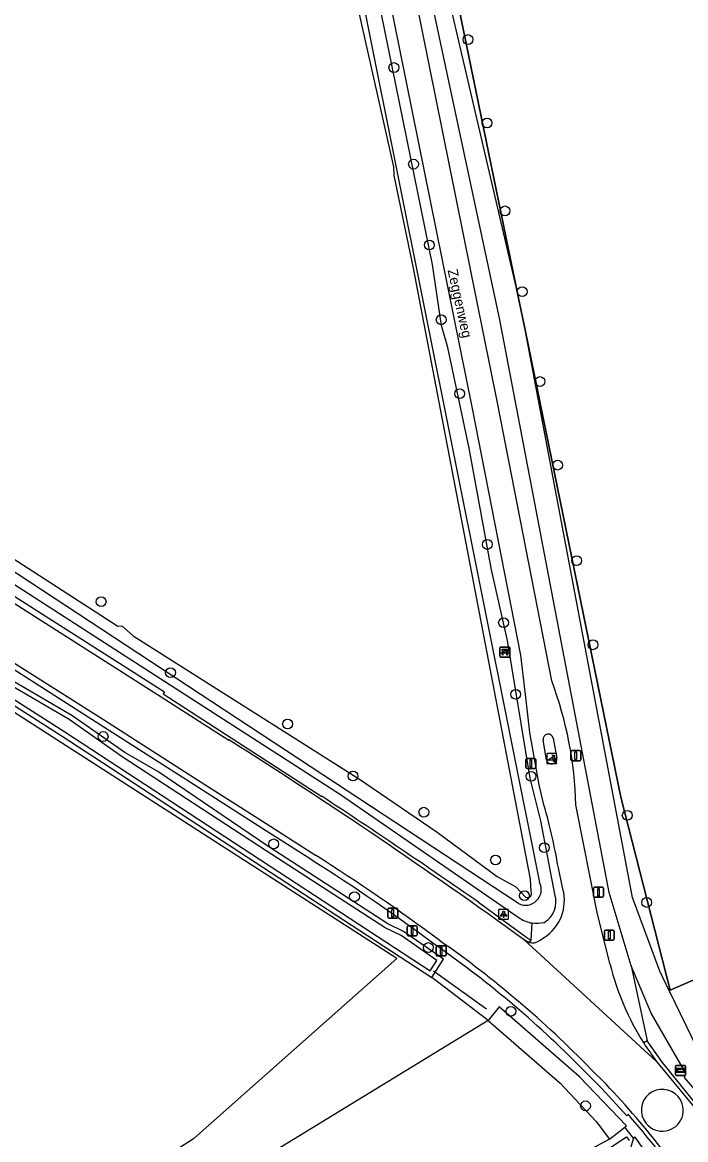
# Model space of a CAD drawing. Extents: x 164494 to 166241, y 382475 to 384494.
# Drawn here: x 165322.7 to 165388.9, y 382859.1 to 382970.6 of the extents above; entities that cross this region are included whole.
import ezdxf

# ---------------------------------------------------------------- set-up
doc = ezdxf.new("R2010")
doc.units = 0
for name, color, linetype in [('IMGEO_Afsluitpaal', 7, 'Continuous'), ('IMGEO_Bank', 7, 'Continuous'), ('IMGEO_Berm_halfverhard', 7, 'Continuous'), ('IMGEO_Boom', 7, 'Continuous'), ('IMGEO_Duiker', 7, 'Continuous'), ('IMGEO_Grasland_agrarisch', 7, 'Continuous'), ('IMGEO_Grasland_overig', 7, 'Continuous'), ('IMGEO_Groenvoorziening', 7, 'Continuous'), ('IMGEO_Hek', 7, 'Continuous'), ('IMGEO_Lichtpunt', 7, 'Continuous'), ('IMGEO_Loofbos', 7, 'Continuous'), ('IMGEO_Openbare_ruimte_label', 7, 'Continuous'), ('IMGEO_Poller', 7, 'Continuous'), ('IMGEO_Rijbaan_lokaal_gesloten', 7, 'Continuous'), ('IMGEO_Rijbaan_lokaal_open', 7, 'Continuous'), ('IMGEO_Verkeersbordpaal', 7, 'Continuous'), ('IMGEO_Waterloop', 7, 'Continuous'), ('IMGEO_Wegwijzer', 7, 'Continuous')]:
    doc.layers.add(name, color=color, linetype=linetype)

msp = doc.modelspace()

# ---------------------------------------------------------------- linework, layer by layer
at = {"layer": 'IMGEO_Afsluitpaal'}
for p, q in [((165377.39, 382897.04), (165377.39, 382897.84)), ((165377.39, 382897.84), (165377.39, 382897.04)), ((165377.49, 382897.94), (165378.28, 382897.94)), ((165378.28, 382897.94), (165377.49, 382897.94)), ((165378.38, 382897.84), (165378.38, 382897.04)), ((165378.38, 382897.04), (165378.38, 382897.84)), ((165372.91, 382896.26), (165372.91, 382897.06)), ((165372.91, 382897.06), (165372.91, 382896.26)), ((165373.01, 382897.16), (165373.8, 382897.16)), ((165373.8, 382897.16), (165373.01, 382897.16)), ((165373.8, 382896.16), (165373.01, 382896.16)), ((165373.01, 382896.16), (165373.8, 382896.16)), ((165373.9, 382897.06), (165373.9, 382896.26)), ((165373.9, 382896.26), (165373.9, 382897.06)), ((165378.28, 382896.94), (165377.49, 382896.94)), ((165377.49, 382896.94), (165378.28, 382896.94)), ((165359.14, 382881.34), (165359.14, 382882.14)), ((165359.14, 382882.14), (165359.14, 382881.34)), ((165359.24, 382882.24), (165360.02, 382882.24)), ((165360.02, 382882.24), (165359.24, 382882.24)), ((165360.12, 382882.14), (165360.12, 382881.34)), ((165360.12, 382881.34), (165360.12, 382882.14)), ((165360.02, 382881.24), (165359.24, 382881.24)), ((165359.24, 382881.24), (165360.02, 382881.24)), ((165361.07, 382879.57), (165361.07, 382880.37)), ((165361.07, 382880.37), (165361.07, 382879.57)), ((165361.17, 382880.47), (165361.95, 382880.47)), ((165361.95, 382880.47), (165361.17, 382880.47)), ((165361.95, 382879.47), (165361.17, 382879.47)), ((165361.17, 382879.47), (165361.95, 382879.47)), ((165362.05, 382880.37), (165362.05, 382879.57)), ((165362.05, 382879.57), (165362.05, 382880.37)), ((165363.96, 382877.56), (165363.96, 382878.36)), ((165363.96, 382878.36), (165363.96, 382877.56)), ((165364.06, 382878.46), (165364.85, 382878.46)), ((165364.85, 382878.46), (165364.06, 382878.46)), ((165364.95, 382878.36), (165364.95, 382877.56)), ((165364.95, 382877.56), (165364.95, 382878.36)), ((165364.85, 382877.46), (165364.06, 382877.46)), ((165364.06, 382877.46), (165364.85, 382877.46))]:
    msp.add_line(p, q, dxfattribs=at)
for points in [[(165377.81, 382897.81), (165377.96, 382897.81), (165377.96, 382897.06), (165377.81, 382897.06), (165377.81, 382897.81)], [(165373.33, 382897.03), (165373.48, 382897.03), (165373.48, 382896.28), (165373.33, 382896.28), (165373.33, 382897.03)], [(165359.55, 382882.11), (165359.71, 382882.11), (165359.71, 382881.36), (165359.55, 382881.36), (165359.55, 382882.11)], [(165361.49, 382880.35), (165361.64, 382880.35), (165361.64, 382879.6), (165361.49, 382879.6), (165361.49, 382880.35)], [(165364.38, 382878.34), (165364.53, 382878.34), (165364.53, 382877.59), (165364.38, 382877.59), (165364.38, 382878.34)]]:
    msp.add_lwpolyline(points, dxfattribs=at)
for centre, start, end in [((165377.49, 382897.84), 90, 180), ((165377.49, 382897.84), 90, 180), ((165378.28, 382897.84), 0, 90), ((165378.28, 382897.84), 360, 90), ((165373.01, 382897.06), 90, 180), ((165373.01, 382897.06), 90, 180), ((165373.01, 382896.26), 180, 270), ((165373.01, 382896.26), 180, 270), ((165373.8, 382897.06), 0, 90), ((165373.8, 382897.06), 360, 90), ((165373.8, 382896.26), 270, 0), ((165373.8, 382896.26), 270, 0), ((165377.49, 382897.04), 180, 270), ((165377.49, 382897.04), 180, 270), ((165378.28, 382897.04), 270, 0), ((165378.28, 382897.04), 270, 0), ((165359.24, 382882.14), 90, 180), ((165359.24, 382882.14), 90, 180), ((165360.02, 382882.14), 0, 90), ((165360.02, 382882.14), 360, 90), ((165359.24, 382881.34), 180, 270), ((165359.24, 382881.34), 180, 270), ((165360.02, 382881.34), 270, 0), ((165360.02, 382881.34), 270, 0), ((165361.17, 382880.37), 90, 180), ((165361.17, 382880.37), 90, 180), ((165361.17, 382879.57), 180, 270), ((165361.17, 382879.57), 180, 270), ((165361.95, 382880.37), 0, 90), ((165361.95, 382880.37), 360, 90), ((165361.95, 382879.57), 270, 0), ((165361.95, 382879.57), 270, 0), ((165364.06, 382878.36), 90, 180), ((165364.06, 382878.36), 90, 180), ((165364.85, 382878.36), 0, 90), ((165364.85, 382878.36), 360, 90), ((165364.06, 382877.56), 180, 270), ((165364.06, 382877.56), 180, 270), ((165364.85, 382877.56), 270, 0), ((165364.85, 382877.56), 270, 0)]:
    msp.add_arc(centre, 0.1, start, end, dxfattribs=at)
at = {"layer": 'IMGEO_Bank'}
for p, q in [((165370.32, 382907.35), (165370.32, 382908.19)), ((165370.32, 382908.19), (165370.32, 382907.35)), ((165370.39, 382908.27), (165371.23, 382908.27)), ((165371.23, 382908.27), (165370.39, 382908.27)), ((165370.62, 382907.78), (165370.62, 382907.88)), ((165371.01, 382907.67), (165370.62, 382907.67)), ((165370.96, 382907.89), (165370.67, 382907.89)), ((165370.67, 382907.88), (165370.67, 382907.78)), ((165370.67, 382907.77), (165370.96, 382907.77)), ((165370.96, 382907.78), (165370.96, 382907.88)), ((165371.01, 382907.88), (165371.01, 382907.78)), ((165371.31, 382908.2), (165371.31, 382907.36)), ((165371.31, 382907.36), (165371.31, 382908.2)), ((165371.24, 382907.27), (165370.4, 382907.27)), ((165370.4, 382907.27), (165371.24, 382907.27))]:
    msp.add_line(p, q, dxfattribs=at)
for points in [[(165370.56, 382907.67), (165370.42, 382907.67), (165370.53, 382907.77), (165370.62, 382907.77)], [(165370.62, 382907.89), (165370.53, 382907.89), (165370.53, 382908.05), (165371.1, 382908.05), (165371.1, 382907.89), (165371.01, 382907.89)], [(165370.61, 382907.66), (165370.61, 382907.46), (165370.57, 382907.46), (165370.57, 382907.66)], [(165371.01, 382907.77), (165371.1, 382907.77), (165371.21, 382907.67), (165371.07, 382907.67)], [(165371.06, 382907.66), (165371.06, 382907.46), (165371.02, 382907.46), (165371.02, 382907.66)]]:
    msp.add_lwpolyline(points, dxfattribs=at)
for centre, radius, start, end in [((165370.39, 382908.19), 0.0779, 92.4484, 184.2845), ((165370.39, 382908.19), 0.0779, 92.4484, 184.2845), ((165370.39, 382907.35), 0.0779, 182.4484, 274.2845), ((165370.39, 382907.35), 0.0779, 182.4484, 274.2845), ((165370.56, 382907.66), 0.00671, 2.8957, 87.1043), ((165370.62, 382907.66), 0.00671, 92.8957, 177.1043), ((165370.62, 382907.88), 0.00671, 2.8957, 87.1043), ((165370.62, 382907.78), 0.00671, 272.8957, 357.1043), ((165370.67, 382907.88), 0.00671, 92.8957, 177.1043), ((165370.67, 382907.78), 0.00671, 182.8957, 267.1043), ((165370.96, 382907.88), 0.00671, 2.8957, 87.1043), ((165370.96, 382907.78), 0.00671, 272.8957, 357.1043), ((165371.01, 382907.88), 0.00671, 92.8957, 177.1043), ((165371.01, 382907.78), 0.00671, 182.8957, 267.1043), ((165371.01, 382907.66), 0.00671, 2.8957, 87.1043), ((165371.07, 382907.66), 0.00671, 92.8957, 177.1043), ((165371.24, 382908.19), 0.0779, 2.4484, 94.2845), ((165371.24, 382908.19), 0.0779, 2.4484, 94.2845), ((165371.24, 382907.35), 0.0779, 272.4484, 4.2845), ((165371.24, 382907.35), 0.0779, 272.4484, 4.2845)]:
    msp.add_arc(centre, radius, start, end, dxfattribs=at)
at = {"layer": 'IMGEO_Berm_halfverhard'}
for points in [[(165252.94, 382956.51), (165253.27, 382957.02), (165336.85, 382903.81), (165336.73, 382903.62), (165352.54, 382893.38)], [(165351.59, 382887), (165346.66, 382890.15), (165339.82, 382894.53), (165330.45, 382900.53), (165322.57, 382905.52), (165313.17, 382911.49), (165304.23, 382917.2), (165295.7, 382922.63), (165290.59, 382925.86), (165282.82, 382930.8), (165276, 382935.15), (165269.08, 382939.56), (165261.99, 382944.04), (165250.07, 382951.57), (165250.4, 382952.08)], [(165368.18, 382882.81), (165373.02, 382879.3), (165373.39, 382879.04)], [(165373.39, 382879.04), (165373.23, 382878.8)], [(165385.01, 382868.98), (165384.67, 382868.78)], [(165405.31, 382840.85), (165405.7, 382841.13), (165395.37, 382856.06), (165395.18, 382855.94), (165395.15, 382855.99), (165390.91, 382861.46), (165386.55, 382866.83), (165385.01, 382868.98)], [(165383.14, 382861.64), (165382.99, 382861.5), (165380.49, 382864.24), (165378.96, 382865.76)]]:
    msp.add_lwpolyline(points, dxfattribs=at)
for centre, radius, start, end in [((165012.37, 382373.04), 621.67, 55.08545, 56.82581), ((165250.17, 382726.04), 190.24, 53.257, 57.7856), ((165304.44, 382793.22), 104, 44.2296, 55.0756), ((165318.7, 382805.39), 85.53, 37.6329, 41.118)]:
    msp.add_arc(centre, radius, start, end, dxfattribs=at)
at = {"layer": 'IMGEO_Boom'}
for centre in [(165367.14, 382968.87), (165359.74, 382966.08), (165369.04, 382960.55), (165361.7, 382956.44), (165370.82, 382951.78), (165363.27, 382948.38), (165372.54, 382943.73), (165364.46, 382940.92), (165374.32, 382934.76), (165366.3, 382933.55), (165376.09, 382926.42), (165369.06, 382918.51), (165377.98, 382916.9), (165330.53, 382912.8), (165370.68, 382910.71), (165379.6, 382908.5), (165337.45, 382905.72), (165371.89, 382903.55), (165349.13, 382900.6), (165330.73, 382899.35), (165355.66, 382895.41), (165373.43, 382895.38), (165362.73, 382891.8), (165383.02, 382891.48), (165347.74, 382888.64), (165374.75, 382888.26), (165369.88, 382887.04), (165372.77, 382883.47), (165355.81, 382883.38), (165384.96, 382882.8), (165363.17, 382878.3), (165371.41, 382871.94), (165378.86, 382862.51)]:
    msp.add_circle(centre, 0.489, dxfattribs=at)
at = {"layer": 'IMGEO_Duiker'}
msp.add_lwpolyline([(165363.68, 382875.99), (165368.98, 382872.18)], dxfattribs=at)
at = {"layer": 'IMGEO_Grasland_agrarisch'}
for points in [[(165373.43, 382883.9), (165373.38, 382885.12), (165361.69, 382946.07), (165359.77, 382955.3), (165359.73, 382956.18), (165356.23, 382971.7), (165355.68, 382973.4), (165355.57, 382974.98), (165351.45, 382995.91), (165350.65, 383000), (165350.07, 383002.18), (165350.07, 383003.02), (165348.36, 383010.36), (165348.14, 383011.31), (165347.08, 383015.04), (165345.31, 383024.57), (165344.87, 383027.57), (165344.77, 383029.04)], [(165240.44, 382969.54), (165240.65, 382969.41), (165269.04, 382951.11), (165283.23, 382941.96), (165296.82, 382933.2), (165304.27, 382928.28), (165316.97, 382920.29), (165318.03, 382919.42), (165318.5, 382918.84), (165319.92, 382918.27), (165332.19, 382910.35), (165332.59, 382910.4), (165333.72, 382909.38), (165356.3, 382895.09), (165364.07, 382889.81), (165370.04, 382885.4), (165371.91, 382884.35), (165372.87, 382883.34)], [(165372.86, 382939.74), (165382.4, 382893.29), (165387.31, 382874.04)]]:
    msp.add_lwpolyline(points, dxfattribs=at)
msp.add_arc((165373.07, 382883.7), 0.412, 240.6912, 28.6949, dxfattribs=at)
at = {"layer": 'IMGEO_Grasland_overig'}
for points in [[(165362.51, 382988.43), (165363.72, 382984.2), (165372.17, 382943.09)], [(165373.5, 382880.75), (165373.39, 382879.04)], [(165383.4, 382876.48), (165385.01, 382868.98)], [(165388.88, 382865.77), (165388.7, 382865.33), (165390.11, 382863.71), (165390.42, 382863.86)]]:
    msp.add_lwpolyline(points, dxfattribs=at)
at = {"layer": 'IMGEO_Groenvoorziening'}
for points in [[(165363.51, 382875.32), (165364.7, 382877.15), (165360.69, 382879.91), (165359.12, 382880.68), (165347.27, 382888.35), (165336.18, 382895.87), (165332.89, 382897.74), (165327.6, 382901.45), (165321.86, 382904.8), (165319.31, 382906.62), (165312.22, 382911.06), (165307.64, 382913.72), (165303.7, 382916.7), (165300.05, 382918.77), (165297.15, 382921.02), (165292.89, 382923.56), (165289.84, 382925.08), (165285.28, 382928.29), (165284.46, 382928.79), (165274.52, 382934.91), (165273.65, 382935.73)], [(165383.66, 382859.29), (165382.79, 382860.38)]]:
    msp.add_lwpolyline(points, dxfattribs=at)
at = {"layer": 'IMGEO_Hek'}
for points in [[(165372.17, 382943.09), (165363.72, 382984.2)], [(165372.86, 382939.74), (165372.17, 382943.09)], [(165486.67, 382941.15), (165464.26, 382919.9), (165449.26, 382899.22), (165420.87, 382884.69), (165401.8, 382879.59), (165395.54, 382877.65), (165387.31, 382874.04)], [(165387.31, 382874.04), (165382.4, 382893.29), (165372.86, 382939.74)], [(165339.77, 382859.26), (165360.03, 382877.2), (165305.75, 382912.08), (165284.75, 382925.67)]]:
    msp.add_lwpolyline(points, dxfattribs=at)
msp.add_arc((165305.48, 382911.5), 62.48, 286.7755, 303.2765, dxfattribs=at)
at = {"layer": 'IMGEO_Lichtpunt'}
for p, q in [((165370.19, 382882.02), (165370.19, 382881.21)), ((165370.19, 382882.02), (165370.19, 382881.21)), ((165371.09, 382882.11), (165370.28, 382882.11)), ((165371.09, 382882.11), (165370.28, 382882.11)), ((165371.18, 382881.21), (165371.18, 382882.02)), ((165371.18, 382881.21), (165371.18, 382882.02)), ((165370.28, 382881.12), (165371.09, 382881.12)), ((165370.28, 382881.12), (165371.09, 382881.12))]:
    msp.add_line(p, q, dxfattribs=at)
for points in [[(165370.56, 382881.68), (165370.6, 382881.66), (165370.41, 382881.39), (165370.37, 382881.42), (165370.56, 382881.68)], [(165370.77, 382881.66), (165370.81, 382881.68), (165371, 382881.42), (165370.96, 382881.39), (165370.77, 382881.66)], [(165370.66, 382881.64), (165370.71, 382881.64), (165370.71, 382881.31), (165370.66, 382881.31), (165370.66, 382881.64)]]:
    msp.add_lwpolyline(points, dxfattribs=at)
msp.add_circle((165370.69, 382881.82), 0.0994, dxfattribs=at)
for centre, start, end in [((165370.28, 382882.02), 90, 180), ((165370.28, 382882.02), 90, 180), ((165371.09, 382882.02), 0, 90), ((165371.09, 382882.02), 0, 90), ((165370.28, 382881.21), 180, 270), ((165370.28, 382881.21), 180, 270), ((165371.09, 382881.21), 270, 0), ((165371.09, 382881.21), 270, 360)]:
    msp.add_arc(centre, 0.0946, start, end, dxfattribs=at)
at = {"layer": 'IMGEO_Loofbos'}
for points in [[(165339.77, 382859.26), (165360.03, 382877.2), (165305.75, 382912.08), (165284.75, 382925.67), (165260.58, 382941.3), (165247.02, 382950.24)], [(165247.02, 382950.24), (165260.73, 382941.64), (165271.58, 382934.54), (165284.7, 382926.17), (165326.65, 382899.4), (165363.51, 382875.32)], [(165387.31, 382874.04), (165395.54, 382877.65), (165401.8, 382879.59), (165420.87, 382884.69), (165449.26, 382899.22), (165464.26, 382919.9), (165486.67, 382941.15)], [(165369.14, 382871.01), (165363.51, 382875.32)], [(165387.31, 382874.04), (165387.21, 382873.99)], [(165369.14, 382871.01), (165324.33, 382843.63), (165321.12, 382842.04), (165316.68, 382840.98), (165307.64, 382839.37), (165292.87, 382838.64), (165283.57, 382838.17), (165264.01, 382836.63), (165240.67, 382836.81), (165237.15, 382837.43), (165233.6, 382838.92), (165230.06, 382841.12), (165201.01, 382864.46)], [(165381.26, 382859.18), (165354.57, 382844.83)]]:
    msp.add_lwpolyline(points, dxfattribs=at)
msp.add_arc((165305.48, 382911.5), 62.48, 286.7755, 303.2765, dxfattribs=at)
at = {"layer": 'IMGEO_Poller'}
for p, q in [((165374.99, 382897.55), (165374.99, 382896.74)), ((165374.99, 382897.55), (165374.99, 382896.74)), ((165375.89, 382897.65), (165375.08, 382897.65)), ((165375.89, 382897.65), (165375.08, 382897.65)), ((165375.98, 382896.74), (165375.98, 382897.55)), ((165375.98, 382896.74), (165375.98, 382897.55)), ((165375.08, 382896.65), (165375.89, 382896.65)), ((165375.08, 382896.65), (165375.89, 382896.65))]:
    msp.add_line(p, q, dxfattribs=at)
for points in [[(165375.62, 382897), (165375.11, 382897), (165375.54, 382897.28)], [(165375.66, 382897.37), (165375.65, 382897.3), (165375.53, 382897.51)], [(165375.53, 382897.51), (165375.76, 382897.44), (165375.69, 382897.41)], [(165375.68, 382896.83), (165375.75, 382897.06), (165375.78, 382896.99)], [(165375.81, 382896.97), (165375.89, 382896.95), (165375.68, 382896.83)]]:
    msp.add_lwpolyline(points, dxfattribs=at)
for centre, radius, start, end in [((165375.08, 382897.55), 0.0946, 90, 180), ((165375.08, 382897.55), 0.0946, 90, 180), ((165375.29, 382897.05), 0.332, 351.3247, 42.4854), ((165375.31, 382897.06), 0.476, 351.7527, 41.1691), ((165375.31, 382897.06), 0.516, 349.3569, 42.2912), ((165375.89, 382897.55), 0.0946, 0, 90), ((165375.89, 382897.55), 0.0946, 0, 90), ((165375.08, 382896.74), 0.0946, 180, 270), ((165375.08, 382896.74), 0.0946, 180, 270), ((165375.89, 382896.74), 0.0946, 270, 0), ((165375.89, 382896.74), 0.0946, 270, 0)]:
    msp.add_arc(centre, radius, start, end, dxfattribs=at)
at = {"layer": 'IMGEO_Rijbaan_lokaal_gesloten'}
for points in [[(165375.49, 382904.9), (165370.09, 382932.65), (165356.47, 383000), (165350.78, 383028.12)], [(165374.6, 382892.96), (165374.25, 382894.54), (165373.3, 382899.75), (165372.93, 382902.96), (165372.4, 382907.45), (165367.54, 382932.22), (165353.85, 383000), (165348.28, 383027.6)], [(165252.94, 382956.51), (165336.52, 382903.3), (165343.27, 382899)], [(165250.4, 382952.08), (165262.31, 382944.54), (165269.4, 382940.07), (165276.32, 382935.66), (165283.14, 382931.31), (165290.91, 382926.37), (165296.02, 382923.13), (165304.55, 382917.7), (165313.49, 382911.99), (165322.89, 382906.02), (165330.77, 382901.04), (165340.15, 382895.04), (165346.98, 382890.66), (165351.91, 382887.51)], [(165374.97, 382897.03), (165374.62, 382899)], [(165375.64, 382899.18), (165376.01, 382897.19)], [(165381.33, 382876.62), (165380.05, 382881.64), (165377.89, 382892.52)], [(165376.6, 382884.12), (165376.16, 382886.24)], [(165373.23, 382878.8), (165372.74, 382879.06)], [(165372.74, 382879.06), (165385.95, 382866.94)], [(165374.28, 382879.01), (165374.74, 382879.31)], [(165379.39, 382866.18), (165380.92, 382864.66)], [(165385.95, 382866.94), (165390.5, 382861.41), (165394.87, 382855.73), (165405.21, 382840.78)]]:
    msp.add_lwpolyline(points, dxfattribs=at)
for centre, radius, start, end in [((165340.63, 382891.73), 37.26, 1.2167, 20.6992), ((165375.14, 382899.07), 0.516, 11.4792, 187.9384), ((165055.3, 382441.82), 540.32, 54.0196, 57.7937), ((165375.48, 382897.14), 0.527, 192.9839, 4.9727), ((165315.47, 382875.7), 61.59, 9.8523, 16.269), ((165250.17, 382726.05), 190.84, 53.2546, 57.782), ((165372.36, 382883), 4.39, 302.7883, 14.7843), ((165304.44, 382793.23), 104.59, 44.2283, 55.0649), ((165373.54, 382879.98), 1.22, 255.3992, 307.555), ((165407.22, 382883.03), 26.68, 193.906, 212.2953), ((165406.99, 382882.89), 26.4, 212.3054, 217.1627), ((165318.84, 382805.51), 85.74, 37.6324, 43.6202)]:
    msp.add_arc(centre, radius, start, end, dxfattribs=at)
at = {"layer": 'IMGEO_Rijbaan_lokaal_open'}
for centre, start, end in [((165386.51, 382862.08), 40.3176, 219.5719), ((165386.53, 382862.06), 218.7266, 41.1628)]:
    msp.add_arc(centre, 2.08, start, end, dxfattribs=at)
at = {"layer": 'IMGEO_Verkeersbordpaal'}
for p, q in [((165379.66, 382883.42), (165379.66, 382884.22)), ((165379.66, 382884.22), (165379.66, 382883.42)), ((165379.76, 382884.32), (165380.55, 382884.32)), ((165380.55, 382884.32), (165379.76, 382884.32)), ((165380.65, 382884.22), (165380.65, 382883.42)), ((165380.65, 382883.42), (165380.65, 382884.22)), ((165380.55, 382883.32), (165379.76, 382883.32)), ((165379.76, 382883.32), (165380.55, 382883.32)), ((165380.74, 382879.14), (165380.74, 382879.94)), ((165380.74, 382879.94), (165380.74, 382879.14)), ((165380.84, 382880.04), (165381.63, 382880.04)), ((165381.63, 382880.04), (165380.84, 382880.04)), ((165381.73, 382879.94), (165381.73, 382879.14)), ((165381.73, 382879.14), (165381.73, 382879.94)), ((165381.63, 382879.04), (165380.84, 382879.04)), ((165380.84, 382879.04), (165381.63, 382879.04))]:
    msp.add_line(p, q, dxfattribs=at)
for points in [[(165380.08, 382884.19), (165380.23, 382884.19), (165380.23, 382883.44), (165380.08, 382883.44), (165380.08, 382884.19)], [(165381.16, 382879.92), (165381.31, 382879.92), (165381.31, 382879.17), (165381.16, 382879.17), (165381.16, 382879.92)]]:
    msp.add_lwpolyline(points, dxfattribs=at)
for centre, start, end in [((165379.76, 382884.22), 90, 180), ((165379.76, 382884.22), 90, 180), ((165380.55, 382884.22), 0, 90), ((165380.55, 382884.22), 360, 90), ((165379.76, 382883.42), 180, 270), ((165379.76, 382883.42), 180, 270), ((165380.55, 382883.42), 270, 0), ((165380.55, 382883.42), 270, 0), ((165380.84, 382879.94), 90, 180), ((165380.84, 382879.94), 90, 180), ((165381.63, 382879.94), 0, 90), ((165381.63, 382879.94), 360, 90), ((165380.84, 382879.14), 180, 270), ((165380.84, 382879.14), 180, 270), ((165381.63, 382879.14), 270, 0), ((165381.63, 382879.14), 270, 0)]:
    msp.add_arc(centre, 0.1, start, end, dxfattribs=at)
at = {"layer": 'IMGEO_Waterloop'}
for points in [[(165345.61, 383027.8), (165374.27, 382884.79)], [(165375.79, 382883.61), (165374.39, 382890.95), (165373.33, 382895.2), (165371.09, 382908.93), (165369.47, 382915.96), (165367.25, 382928.1), (165365.11, 382938.17), (165364.5, 382940.34), (165363.59, 382946.42), (165352.67, 383000), (165350.36, 383011.32), (165348.81, 383020.43), (165347.25, 383028.22)], [(165156.81, 383024.45), (165162.98, 383018.91), (165183.62, 383000.36), (165208.01, 382978.45), (165217.25, 382970.44), (165247.28, 382950.65), (165260.99, 382942.05), (165271.84, 382934.95), (165284.96, 382926.58), (165326.91, 382899.81), (165363.36, 382875.99), (165364.03, 382877.02), (165360.45, 382879.49), (165358.88, 382880.26), (165347, 382887.94), (165332.63, 382897.34), (165327.34, 382901.05), (165321.6, 382904.4), (165319.04, 382906.22), (165311.97, 382910.64), (165307.37, 382913.32)], [(165383.4, 382876.48), (165381.21, 382883.79), (165370.3, 382940.92), (165362.23, 382978.76), (165362.71, 382978.93), (165363.71, 382979.28), (165372.17, 382943.09)], [(165372.18, 382882.69), (165322.04, 382915.66), (165240.83, 382968.43), (165240.58, 382968.58), (165240.33, 382968.7), (165240.07, 382968.78), (165239.92, 382968.79), (165239.53, 382968.72), (165239.31, 382968.56), (165239.13, 382968.23), (165239.1, 382968.04), (165239.09, 382967.96), (165239.07, 382967.68)], [(165239.07, 382967.68), (165239.21, 382967.57), (165239.45, 382967.33), (165271.46, 382946.73), (165303.61, 382926.18), (165319.21, 382916.2), (165335.92, 382905.46), (165354.4, 382893.57), (165372.35, 382881.21)], [(165372.17, 382943.09), (165372.86, 382939.74)], [(165387.21, 382873.99), (165386.26, 382875.95), (165383.56, 382883.3), (165372.86, 382939.74)], [(165388.88, 382865.77), (165385.41, 382871.77), (165383.4, 382876.48)], [(165387.21, 382873.99), (165389.96, 382868.28)], [(165382.79, 382860.38), (165382.94, 382860.53), (165378.27, 382865.39), (165370.25, 382872.37), (165369.14, 382871.01)], [(165369.14, 382871.01), (165376.3, 382864.79), (165379.93, 382860.95), (165381.26, 382859.18)], [(165378.74, 382856.61), (165382.95, 382859.42), (165383.2, 382859.04)], [(165381.26, 382859.18), (165382.79, 382860.38)], [(165395.48, 382838.57), (165397.12, 382839.61), (165390.74, 382849.5), (165383.82, 382859.4), (165383.66, 382859.29)], [(165383.66, 382859.29), (165383.04, 382857.32)]]:
    msp.add_lwpolyline(points, dxfattribs=at)
for centre, radius, start, end in [((165372.88, 382884.08), 1.56, 243.102, 26.898), ((165373.54, 382882.85), 2.37, 300.6927, 18.6544), ((165373.99, 382883.67), 2.96, 236.4314, 260.4662), ((165373.94, 382884.66), 3.93, 263.55, 281.8547)]:
    msp.add_arc(centre, radius, start, end, dxfattribs=at)
at = {"layer": 'IMGEO_Wegwijzer'}
for p, q in [((165387.84, 382865.65), (165387.84, 382866.45)), ((165387.84, 382866.45), (165387.84, 382865.65)), ((165387.94, 382866.55), (165388.73, 382866.55)), ((165388.73, 382866.55), (165387.94, 382866.55)), ((165388.83, 382866.45), (165388.83, 382865.65)), ((165388.83, 382865.65), (165388.83, 382866.45)), ((165388.73, 382865.55), (165387.94, 382865.55)), ((165387.94, 382865.55), (165388.73, 382865.55))]:
    msp.add_line(p, q, dxfattribs=at)
for points in [[(165387.94, 382866.28), (165388.73, 382866.28), (165388.73, 382865.82), (165387.94, 382865.82), (165387.94, 382866.28)], [(165388, 382866.14), (165388, 382866.05), (165388, 382865.97), (165388.42, 382865.97), (165388.42, 382865.88), (165388.66, 382866.05), (165388.42, 382866.22), (165388.42, 382866.14), (165388, 382866.14)]]:
    msp.add_lwpolyline(points, dxfattribs=at)
for centre, start, end in [((165387.94, 382866.45), 90, 180), ((165387.94, 382866.45), 90, 180), ((165388.73, 382866.45), 0, 90), ((165388.73, 382866.45), 360, 90), ((165387.94, 382865.65), 180, 270), ((165387.94, 382865.65), 180, 270), ((165388.73, 382865.65), 270, 0), ((165388.73, 382865.65), 270, 0)]:
    msp.add_arc(centre, 0.1, start, end, dxfattribs=at)

# ---------------------------------------------------------------- texts
at = {"layer": 'IMGEO_Openbare_ruimte_label'}
msp.add_text('Zeggenweg', height=1, rotation=282.4108, dxfattribs=at).set_placement((165365.09, 382945.86))

doc.saveas('drawing.dxf')
